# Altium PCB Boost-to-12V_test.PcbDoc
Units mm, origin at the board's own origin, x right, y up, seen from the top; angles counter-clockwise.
Board outline 17.4 x 14.48 mm, 2 copper layers (Top Layer, Bottom Layer); 14 components, 7 nets, 31 pads, 26 vias.
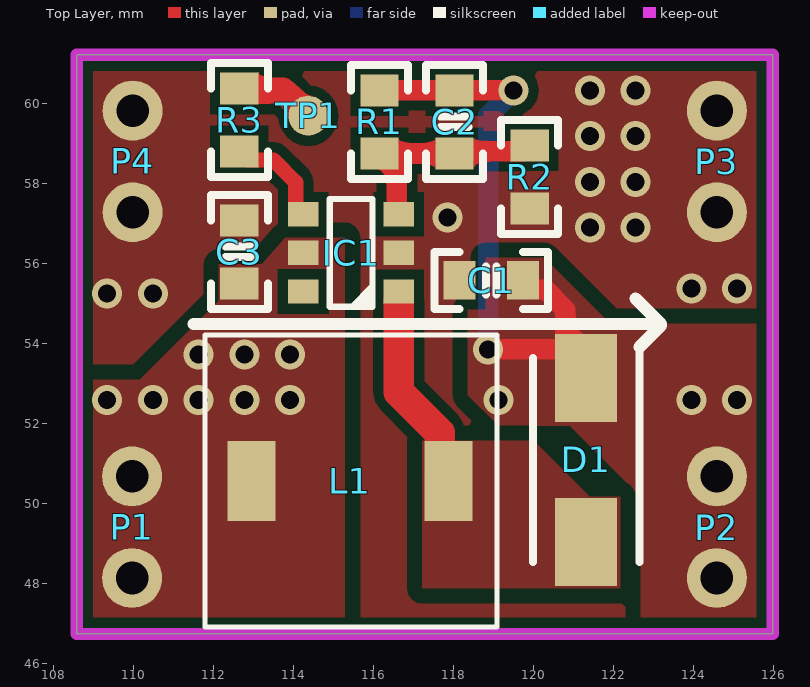
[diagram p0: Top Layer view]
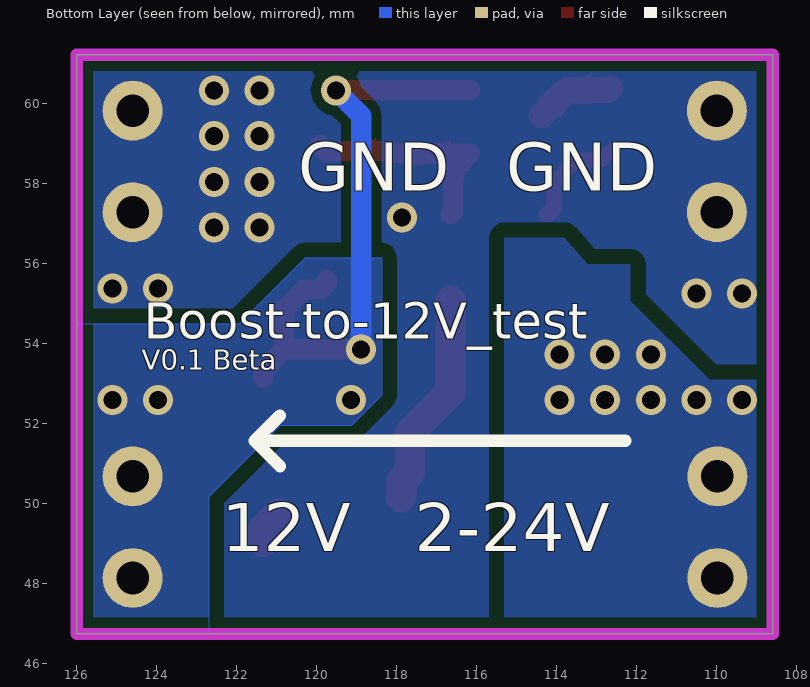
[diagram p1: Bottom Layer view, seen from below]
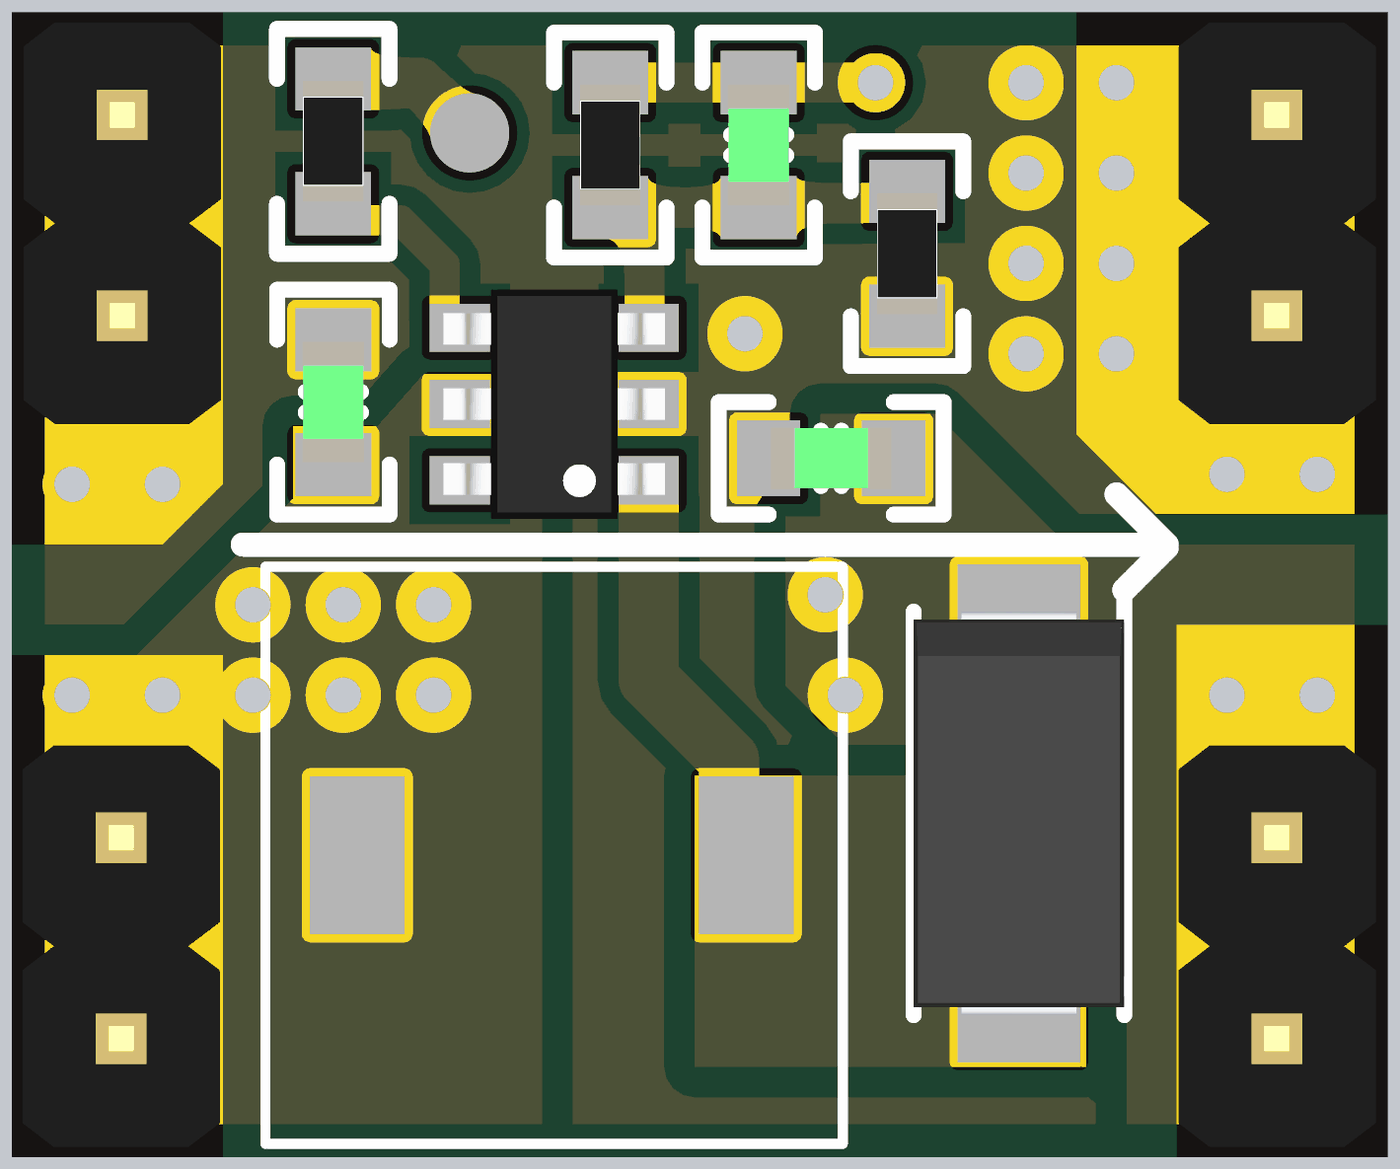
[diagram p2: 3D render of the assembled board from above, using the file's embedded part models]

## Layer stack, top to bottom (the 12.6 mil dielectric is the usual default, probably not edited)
Top Solder: solder mask 0.0102, Solder Resist, Dk 3.5
Top Layer: signal copper 0.0356
Dielectric 1: dielectric 0.32, FR-4, Dk 4.8
Bottom Layer: signal copper 0.0356
Bottom Solder: solder mask 0.0102, Solder Resist, Dk 3.5

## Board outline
108.585,46.736 125.984,46.736 125.984,61.214 108.585,61.214

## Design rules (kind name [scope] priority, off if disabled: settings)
Clearance [All] p1: gap=0.254 ignorepadtopadclearanceinfootprint=FALSE except(0.381: Fill-Fill Fill-Poly Fill-Region Poly-Poly Poly-Region Region-Region)
PlaneConnect [All] p1: planeconnectstyle=Direct reliefexpansion=0.508 reliefentries=4 reliefconductorwidth=0.254 reliefairgap=0.254
PolygonConnect [All] p1: connectstyle=Direct reliefconductorwidth=0.254 reliefentries=4 polygonreliefangle="90 Angle" airgapwidth=0.254
RoutingVias [All] p1: holewidth=0.45 width=0.75 viastyle="Through Hole" minholewidth=0.45 minwidth=0.75 maxholewidth=0.45 maxwidth=0.75
SolderMaskExpansion [All] p1: expansion=0.102 istentingtop=FALSE
Width [All] p1: maxlimit=2.54 minlimit=0.381 preferedwidth=0.381
29 further rules are at their usual default settings.

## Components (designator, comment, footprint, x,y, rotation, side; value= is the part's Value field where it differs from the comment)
C1 "22uF/25V" CAP-0603 118.947,55.574 r0 top
C2 "15pF/50V" CAP-0603 118.03,59.536 r90 top
C3 "22uF/25V" CAP-0603 112.65,56.285 r270 top
D1 "SS34" DO-214AC_SMA 121.322,51.083 r270 top
IC1 "SX1308" SOT-23-6 115.443,56.261 r0 top locked
L1 "4.7uH/4A" SMD_7.3x7.3x4.2mm 114.973,50.183 r0 top
P1 "HDR1x2_2.54" HDR1X2_2.54_180 109.968,50.673 r0 top
P2 "HDR1x2_2.54" HDR1X2_2.54_180 124.587,50.673 r0 top
P3 "HDR1x2_2.54" HDR1X2_2.54_180 124.587,59.817 r0 top
P4 "HDR1x2_2.54" HDR1X2_2.54_180 109.982,59.817 r0 top
R1 "191k" R-0603 116.153,59.536 r90 top
R2 "10k" R-0603 119.906,58.161 r90 top
R3 "100k" R-0603 112.649,59.584 r270 top
TP1 "TestPoint" TestPoint 114.375,59.69 r90 top

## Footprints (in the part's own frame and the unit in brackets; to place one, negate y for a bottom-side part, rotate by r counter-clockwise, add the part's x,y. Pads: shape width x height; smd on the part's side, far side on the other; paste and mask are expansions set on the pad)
CAP-0603 [mm]
  rect 0.8x0.96 smd: 1(-0.79,0) 2(0.79,0)
  silkscreen extent -1.42,-0.71 1.42,0.71, body extent -0.76,-0.39 0.76,0.39, height 0.9
DO-214AC_SMA [mm]
  rect 2.2x1.55 smd: 1(2.05,0) 2(-2.05,0)
  silkscreen extent -2.83,-1.33 2.55,1.33, body extent -2.55,-1.33 2.55,1.33, height 2.29
HDR1X2_2.54_180 [mm]
  round 1.5 hole 0.813: 1(0,0) 2(0,-2.54)
  body extent -1.25,-3.81 1.25,1.27, height 8.2
R-0603 [mm]
  rect 0.8x0.96 smd: 1(-0.79,0) 2(0.79,0)
  silkscreen extent -1.42,-0.71 1.42,0.71, body extent -0.76,-0.38 0.76,0.38, height 0.41
SMD_7.3x7.3x4.2mm [mm]
  rect 1.2x2 smd: 1(-2.02,0.37) 2(2.9,0.37)
  silkscreen extent -3.18,-3.28 4.12,4.02, body extent -3.18,-3.28 4.1,4, height 3
SOT-23-6 [mil]
  rect 30x24 smd: 1(47,-38) 2(47,0) 3(47,38) 4(-47,38) 5(-47,0) 6(-47,-38)
  silkscreen extent -21,-53 21,53, body extent -55,-57 55,57, height 57
TestPoint [mm]
  round 1 smd: 1(0,0)

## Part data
C1 C3: library part CAP, "X7R", Package=0402, SuppliersPartNumber=C52923
C2: library part CAP, "NPO", Package=0402, SuppliersPartNumber=C52923
D1: library part DIODE, "肖特基二极管", Package=SMA(DO-214AC), SuppliersPartNumber=C22452
IC1: "集成升压芯片", Manufacturer_Name="Shenzhen Suosemi Tech"
L1: library part INDUCTOR, "电感", Package=0402, SuppliersPartNumber=C32041
P1 P2 P3 P4: "Header"
R1 R2 R3: library part RES, "贴片电阻", Package=0805, SuppliersPartNumber=C17798
TP1: "测试点"

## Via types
v1: diameter 0.75, hole 0.45, Top Layer to Bottom Layer, 26 vias

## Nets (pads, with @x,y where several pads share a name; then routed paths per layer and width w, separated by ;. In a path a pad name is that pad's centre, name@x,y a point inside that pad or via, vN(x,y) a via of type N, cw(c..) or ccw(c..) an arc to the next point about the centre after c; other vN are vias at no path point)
5V: C3.2 IC1.5 L1.1 P1.1 P1.2
  other v1: 109.347,52.578 110.49,52.578 111.633,52.578 112.776,52.578 113.919,52.578 111.633,53.721 112.776,53.721 113.919,53.721
12V: C1.2 C2.2 D1.2 P2.1 P2.2 R1.2 | length 15.4
  Top Layer w0.508: R1.2 C2.2 ; C2.2@118.03,60.326 v1(119.507,60.325) ; v1(118.872,53.848) D1.2@120.801,53.848 ; C1.2 119.737,55.494 119.883,55.348 120.293,55.348 120.801,54.84 D1.2@120.801,53.848 ; D1.2 121.322,53.327 D1.2@120.801,53.848
  Bottom Layer w0.508: v1(118.872,53.848) 118.872,59.69 v1(119.507,60.325)
  other v1: 119.126,52.578 123.952,52.578 125.095,52.578
EN: R3.1 TP1.1 | length 2
  Top Layer w0.635: R3.1 112.698,60.325 113.74,60.325 TP1.1
GND: C1.1 C3.1 IC1.2 P3.1 P3.2 P4.1 P4.2 R2.1
  other v1: 109.347,55.245 110.49,55.245 123.952,55.372 125.095,55.372 121.412,56.896 122.555,56.896 117.856,57.15 121.412,58.039 122.555,58.039 121.412,59.182 122.555,59.182 121.412,60.325 122.555,60.325
NetC2_1: C2.1 IC1.3 R1.1 R2.2 | length 5.9
  Top Layer w0.508: R1.1@116.586,58.6 116.586,57.277 IC1.3 ; 116.713,58.547 116.66,58.6 116.299,58.6 R1.1 116.233,58.746 C2.1 118.084,58.801 119.326,58.801 119.331,58.805 119.76,58.805 R2.2
NetD1_1: D1.1 IC1.1 L1.2 | length 6.3
  Top Layer w0.762: IC1.1@116.637,55.067 116.637,52.781 117.654,51.764 117.654,50.772 L1.2 L1.2@117.873,50.153 ; D1.1@120.928,49.752 121.322,49.358 D1.1
NetIC1_4: IC1.4 R3.2 | length 2.7
  Top Layer w0.381: R3.2 112.859,58.584 113.501,58.584 114.059,58.026 114.059,57.34 114.173,57.226 IC1.4
pads on no net: IC1.6

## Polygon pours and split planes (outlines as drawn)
12V on Top Layer "12V_L01_P002" (solid, remove dead copper, pour order 2): 125.984,46.736 125.984,54.483 121.92,54.483 120.269,56.134 118.364,56.134 118.364,52.705 119.126,51.943 120.904,51.943 122.682,50.165 122.682,46.736
GND on Top Layer "GND_L01_P003" (solid, remove dead copper, pour order 3): 108.585,61.214 128.143,61.214 128.143,46.736 108.585,46.736
5V on Top Layer "5V_L01_P001" (solid, remove dead copper, pour order 1): 113.792,56.642 113.208,55.982 112.141,55.982 112.141,55.067 110.16,53.086 108.61,53.086 108.61,46.761 115.291,46.761 115.291,56.642
NetD1_1 on Top Layer "NETD1_1_L01_P000" (solid, pour order 0): 122.174,50.165 122.174,47.879 117.221,47.879 117.221,51.562 120.015,51.562 121.412,50.165
5V on Bottom Layer "5V_L02_P007" (solid, remove dead copper, pour order 7): 113.792,56.642 113.208,55.982 112.141,55.982 112.141,55.067 110.16,53.086 108.61,53.086 108.61,46.761 115.291,46.761 115.291,56.642
12V on Bottom Layer "12V_L02_P006" (solid, remove dead copper, pour order 6): 125.984,46.736 125.984,54.483 121.92,54.483 120.269,56.134 118.364,56.134 118.364,52.705 119.126,51.943 120.904,51.943 122.682,50.165 122.682,46.736
no net on Bottom Layer "NONET_L02_P005" (solid, remove dead copper, pour order 5): 125.984,46.736 125.984,54.483 121.92,54.483 120.269,56.134 118.364,56.134 118.364,52.705 119.126,51.943 120.904,51.943 122.682,50.165 122.682,46.736
GND on Bottom Layer "GND_L02_P004" (solid, remove dead copper, pour order 4): 108.585,61.214 130.429,61.214 130.429,46.736 108.585,46.736
5V on Top Solder "NONET_L01_P-001" (solid): 108.585,46.736 111.252,46.736 111.252,53.086 108.585,53.086
GND on Top Solder "NONET_L01_P-001" (solid): 108.585,61.214 108.585,54.483 110.49,54.483 111.252,55.245 111.252,61.214
GND on Top Solder "NONET_L01_P-001" (solid): 125.984,61.214 122.047,61.214 122.047,55.88 123.063,54.864 125.984,54.864
12V on Top Solder "NONET_L01_P-001" (solid): 123.317,46.736 125.984,46.736 125.984,53.467 123.317,53.467

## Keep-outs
Keep-Out Layer:
  the board outline again, w0.305

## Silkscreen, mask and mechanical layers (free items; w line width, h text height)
Top Overlay:
  lines w0.305: 111.506,54.483 123.19,54.483 ; 122.555,55.118 123.19,54.483 ; 122.654,53.908 123.19,54.444 123.19,54.483
Bottom Overlay:
  lines w0.305: 112.268,51.562 121.539,51.562 ; 120.904,50.927 121.539,51.562 ; 120.904,52.197 121.539,51.562
  text "GND" at 115.243,57.82 h1.2
  text "GND" at 120.45,57.82 h1.2
  text "Boost-to-12V_test" at 124.31,54.108 h0.9
  text "V0.1 Beta" at 124.36,53.344 h0.5
  text "2-24V" at 117.529,48.803 h1.2
  text "12V" at 122.355,48.803 h1.2
Mechanical 1:
  the board outline again, w0.305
